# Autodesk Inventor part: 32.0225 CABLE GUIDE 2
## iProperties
Created: 2012-10
Part Number: 32.0225 CABLE GUIDE 2
Document SubType Name: Modeling
Designer: Administrator
Density: 1.4 g/cm^3
Material: PVC-Piping
Mass: 5.14647 g
Surface Area: 23.3811 cm^2
Volume: 3.67605 cm^3
Author: Administrator
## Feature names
1. Base1
